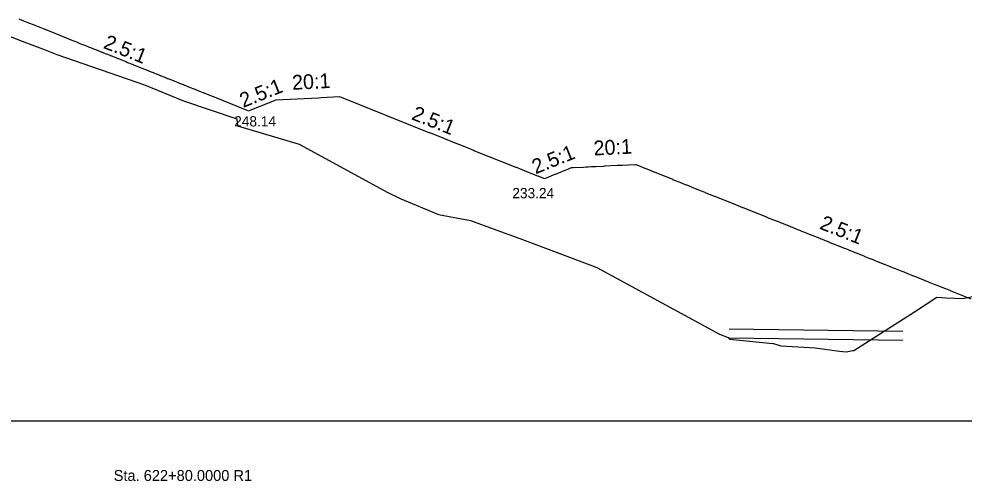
# Model space of a CAD drawing. Extents: x -26 to 1629, y -25 to 9635.
# Drawn here: x 234.5 to 442.3, y 6986.7 to 7088.3 of the extents above; entities that cross this region are included whole.
import ezdxf

# ---------------------------------------------------------------- set-up
doc = ezdxf.new("R2010")
doc.units = 0
for name, color, linetype in [('Draft_XS_Text', 7, 'Continuous'), ('DTM CONTOURS_MAJOR', 7, 'Continuous'), ('DTM_X_GROUND', 7, 'Continuous'), ('XS_CELL', 7, 'Continuous'), ('XS_P_DRAINAGE', 7, 'Continuous'), ('XS_P_GROUND', 7, 'Continuous'), ('XS_P_TX_DCH', 7, 'Continuous'), ('XS_P_TX_FS_BS', 7, 'Continuous')]:
    doc.layers.add(name, color=color, linetype=linetype)

msp = doc.modelspace()

# ---------------------------------------------------------------- linework, layer by layer
at = {"layer": 'DTM_X_GROUND'}
msp.add_lwpolyline([(228.71, 7085.96), (236.21, 7083.05), (240.25, 7081.54), (242.88, 7080.52), (262.1, 7073.86), (270.66, 7070.34), (282.39, 7066.33), (282.57, 7064.81), (296.1, 7060.78), (315.56, 7050.16), (318.27, 7048.85), (326.72, 7045.33), (333.75, 7044.01), (338.98, 7042.12), (345.23, 7039.86), (360.59, 7034.03), (361.54, 7033.69), (388.49, 7019.04), (390.41, 7018.29), (390.64, 7018), (390.76, 7017.91), (400.18, 7016.99), (400.33, 7016.94), (402.01, 7016.43), (409.51, 7015.99), (414.89, 7015.29), (416.32, 7015.1), (417.77, 7015.4), (418.04, 7015.44), (418.8, 7015.93), (431.32, 7023.96), (436.25, 7027.13), (438.28, 7027.03), (442.01, 7026.85), (460.89, 7030.66)], dxfattribs=at)
at = {"layer": 'XS_CELL'}
msp.add_line((100, 7000), (550, 7000), dxfattribs=at)
at = {"layer": 'XS_P_DRAINAGE'}
for p, q in [((390.65, 7020.18), (428.81, 7019.7)), ((390.63, 7018.18), (428.79, 7017.7))]:
    msp.add_line(p, q, dxfattribs=at)
at = {"layer": 'XS_P_GROUND'}
msp.add_lwpolyline([(234.51, 7088.33), (234.66, 7088.27), (235.52, 7087.93), (236.22, 7087.65), (236.84, 7087.4), (237.64, 7087.08), (239.87, 7086.19), (240.8, 7085.82), (245.27, 7084.03), (246.54, 7083.52), (247.14, 7083.28), (247.93, 7082.96), (248.74, 7082.64), (249.02, 7082.53), (249.97, 7082.15), (250.31, 7082.01), (250.37, 7081.99), (250.9, 7081.78), (251.54, 7081.52), (252.71, 7081.05), (252.77, 7081.03), (252.85, 7080.99), (252.92, 7080.97), (253.44, 7080.76), (253.71, 7080.65), (253.96, 7080.55), (254.51, 7080.33), (254.56, 7080.31), (254.65, 7080.28), (254.7, 7080.26), (255.94, 7079.76), (256.26, 7079.63), (256.34, 7079.6), (256.52, 7079.53), (258, 7078.94), (258.4, 7078.78), (259.6, 7078.29), (259.69, 7078.26), (260.04, 7078.12), (260.28, 7078.03), (261.39, 7077.58), (261.41, 7077.57), (261.9, 7077.38), (262.15, 7077.28), (262.97, 7076.95), (263.09, 7076.9), (263.72, 7076.65), (263.83, 7076.6), (264, 7076.54), (264.32, 7076.41), (264.66, 7076.27), (264.8, 7076.22), (264.87, 7076.19), (265.1, 7076.09), (265.73, 7075.84), (265.78, 7075.82), (266.95, 7075.36), (267.19, 7075.26), (267.21, 7075.25), (268.64, 7074.68), (268.69, 7074.66), (268.7, 7074.66), (268.81, 7074.61), (269.54, 7074.32), (269.61, 7074.29), (270.96, 7073.75), (271, 7073.73), (271.81, 7073.41), (272.01, 7073.33), (272.71, 7073.05), (272.81, 7073.01), (274.22, 7072.45), (274.4, 7072.37), (275.07, 7072.11), (275.2, 7072.06), (275.34, 7072), (275.49, 7071.94), (278.87, 7070.59), (279, 7070.54), (284.63, 7068.28), (285, 7068.14), (290.69, 7070.41), (291, 7070.54), (300.38, 7071), (300.95, 7071.03), (304.99, 7071.24), (305, 7071.24), (305.02, 7071.23), (305.36, 7071.09), (324.63, 7063.38), (324.64, 7063.38), (324.72, 7063.35), (327.89, 7062.08), (327.97, 7062.05), (331.14, 7060.78), (331.17, 7060.77), (332.22, 7060.35), (332.28, 7060.32), (334.39, 7059.48), (334.68, 7059.36), (343.74, 7055.74), (343.81, 7055.71), (344, 7055.64), (344.69, 7055.36), (345.57, 7055.01), (345.64, 7054.98), (345.71, 7054.95), (348.52, 7053.83), (348.56, 7053.81), (348.74, 7053.74), (350, 7053.24), (350.44, 7053.41), (352.14, 7054.09), (352.37, 7054.18), (352.44, 7054.21), (355.28, 7055.35), (355.3, 7055.36), (355.47, 7055.42), (356, 7055.64), (356.25, 7055.65), (358.63, 7055.77), (359.18, 7055.8), (359.23, 7055.8), (359.6, 7055.82), (360.35, 7055.85), (361.15, 7055.89), (361.29, 7055.9), (363.12, 7055.99), (363.22, 7056), (366.09, 7056.14), (366.12, 7056.14), (367.08, 7056.19), (367.12, 7056.19), (367.15, 7056.19), (368.48, 7056.26), (370, 7056.34), (370.07, 7056.31), (371.04, 7055.92), (371.89, 7055.58), (372.07, 7055.51), (372.07, 7055.5), (372.12, 7055.49), (373.93, 7054.76), (373.93, 7054.76), (374.08, 7054.7), (374.13, 7054.68), (376.1, 7053.89), (376.15, 7053.87), (378.13, 7053.08), (378.18, 7053.06), (380.16, 7052.26), (380.19, 7052.25), (381.18, 7051.85), (381.21, 7051.84), (382.2, 7051.45), (382.25, 7051.42), (384.25, 7050.62), (384.28, 7050.61), (385.28, 7050.21), (385.33, 7050.19), (387.34, 7049.39), (387.39, 7049.37), (389.41, 7048.56), (389.46, 7048.54), (391.48, 7047.73), (391.51, 7047.72), (392.52, 7047.31), (392.55, 7047.3), (393.57, 7046.89), (393.62, 7046.87), (395.66, 7046.05), (395.68, 7046.04), (396.71, 7045.63), (396.76, 7045.61), (398.81, 7044.79), (398.86, 7044.77), (400.92, 7043.94), (401, 7043.91), (404.11, 7042.67), (404.11, 7042.67), (404.19, 7042.63), (404.22, 7042.62), (405.17, 7042.24), (405.17, 7042.24), (405.26, 7042.2), (405.29, 7042.19), (406.33, 7041.78), (406.36, 7041.76), (407.51, 7041.3), (407.53, 7041.29), (408.38, 7040.96), (408.38, 7040.95), (408.48, 7040.92), (408.5, 7040.91), (409.38, 7040.55), (409.41, 7040.54), (410.53, 7040.09), (410.53, 7040.09), (410.63, 7040.05), (410.68, 7040.03), (412.68, 7039.23), (412.77, 7039.19), (413.89, 7038.74), (414.3, 7038.58), (414.89, 7038.35), (414.97, 7038.31), (415.07, 7038.27), (415.93, 7037.93), (416.2, 7037.82), (416.91, 7037.54), (417.02, 7037.49), (417.03, 7037.49), (417.15, 7037.44), (417.26, 7037.4), (417.93, 7037.13), (418.11, 7037.06), (418.2, 7037.02), (418.24, 7037), (418.26, 7037), (418.51, 7036.9), (419.86, 7036.36), (420.01, 7036.29), (420.23, 7036.21), (420.3, 7036.18), (420.96, 7035.91), (421.73, 7035.6), (421.8, 7035.58), (421.84, 7035.56), (422.42, 7035.33), (422.42, 7035.33), (422.49, 7035.3), (422.86, 7035.15), (423.4, 7034.94), (424.7, 7034.42), (424.71, 7034.41), (424.73, 7034.4), (424.77, 7034.39), (425.43, 7034.12), (425.97, 7033.91), (426.67, 7033.62), (426.87, 7033.54), (426.91, 7033.53), (426.91, 7033.53), (427.08, 7033.46), (427.09, 7033.46), (428.57, 7032.86), (428.63, 7032.84), (429.13, 7032.64), (429.15, 7032.63), (429.31, 7032.56), (429.53, 7032.48), (430.89, 7031.93), (431.09, 7031.86), (431.1, 7031.85), (431.56, 7031.67), (432.38, 7031.34), (432.41, 7031.32), (432.48, 7031.3), (433.33, 7030.95), (433.37, 7030.94), (433.6, 7030.85), (433.61, 7030.84), (433.81, 7030.76), (434.28, 7030.57), (434.35, 7030.55), (435.84, 7029.95), (435.87, 7029.94), (436.97, 7029.5), (436.97, 7029.49), (437.21, 7029.4), (437.21, 7029.4), (438.09, 7029.05), (438.14, 7029.03), (439.23, 7028.59), (439.35, 7028.54), (439.9, 7028.32), (440, 7028.28), (440.09, 7028.25), (441.5, 7027.68), (441.53, 7027.67), (441.77, 7027.57), (441.9, 7027.52), (443.75, 7026.78)], dxfattribs=at)

# ---------------------------------------------------------------- texts
at = {"layer": 'Draft_XS_Text'}
msp.add_text('Sta. 622+80.0000 R1', height=2.4, dxfattribs=at).set_placement((255.34, 6986.75))
at = {"layer": 'DTM CONTOURS_MAJOR'}
for p in [(278.96, 7070.48), (290.96, 7070.48), (304.96, 7071.18), (284.96, 7068.08), (343.96, 7055.58), (355.96, 7055.58), (369.96, 7056.28), (349.96, 7053.18)]:
    msp.add_text('X', height=0.12, dxfattribs=at).set_placement(p)
at = {"layer": 'XS_P_TX_DCH'}
for s, p in [('248.14', (281.82, 7064.69)), ('233.24', (342.96, 7048.91))]:
    msp.add_text(s, height=2.25, dxfattribs=at).set_placement(p)
at = {"layer": 'XS_P_TX_FS_BS'}
for s, rotation, p in [('2.5:1', 338.1986, (252.89, 7081.97)), ('20:1', 2.8624, (294.62, 7072.74)), ('2.5:1', 21.8014, (283.82, 7068.75)), ('2.5:1', 338.1986, (320.6, 7066.31)), ('20:1', 2.8624, (360.89, 7058.3)), ('2.5:1', 21.8014, (348.07, 7054.16)), ('2.5:1', 338.1603, (410.31, 7042.25))]:
    msp.add_text(s, height=3.24, rotation=rotation, dxfattribs=at).set_placement(p)

doc.saveas('drawing.dxf')
